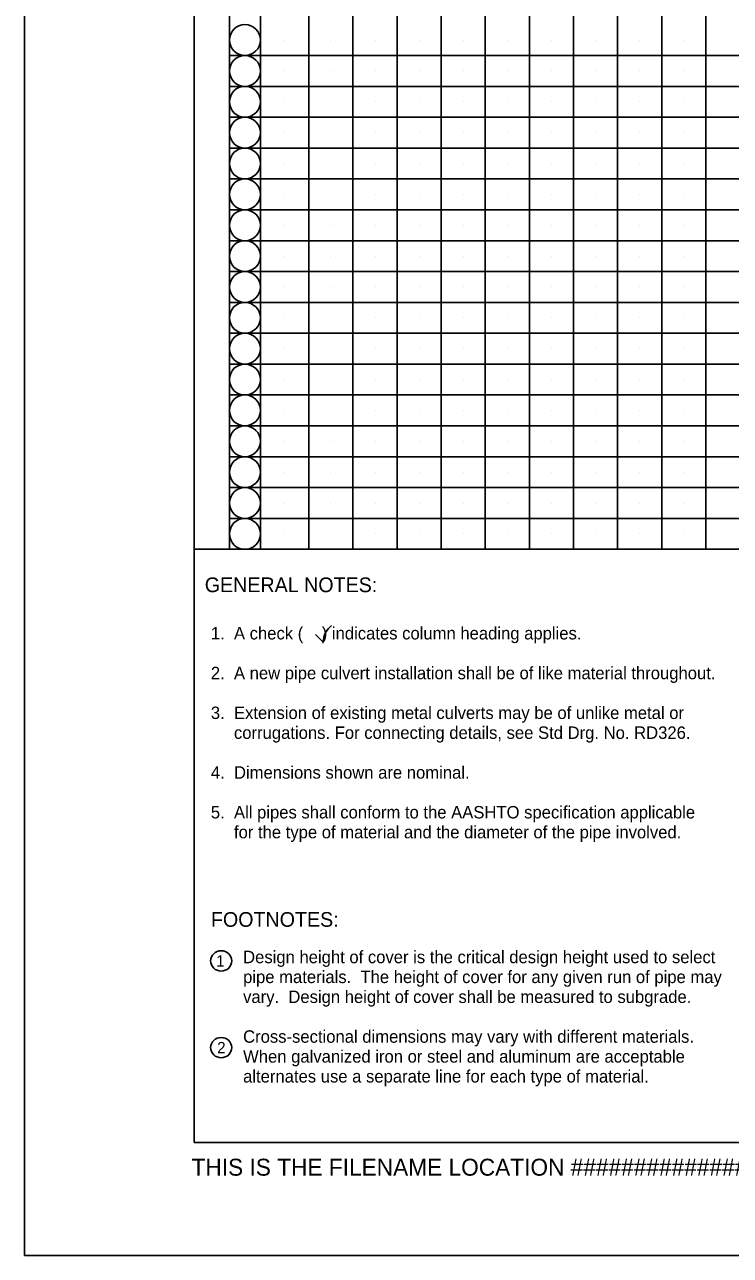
# Model space of a CAD drawing. Extents: x -1700 to 0, y 0 to 1100.
# Drawn here: x -1700 to -1388, y 0 to 545 of the extents above; entities that cross this region are included whole.
import ezdxf

# ---------------------------------------------------------------- set-up
doc = ezdxf.new("R2010")
doc.units = 0
for name, color, linetype in [('#plot_border', 7, 'Continuous'), ('#plot_shape', 7, 'Continuous'), ('P_ODOT_PLAN_Border', 7, 'Continuous'), ('P_ODOT_PLAN_General', 7, 'Continuous'), ('P_RDWY_PLAN_NotesTx', 7, 'Continuous')]:
    doc.layers.add(name, color=color, linetype=linetype)

msp = doc.modelspace()

# ---------------------------------------------------------------- linework, layer by layer
at = {"layer": '#plot_shape'}
msp.add_lwpolyline([(-1700, 0), (0, 0), (0, 1100), (-1700, 1100)], close=True, dxfattribs=at)
at = {"layer": 'P_ODOT_PLAN_Border'}
msp.add_lwpolyline([(-1625, 50), (-25, 50), (-25, 1050), (-1625, 1050)], close=True, dxfattribs=at)
at = {"layer": 'P_ODOT_PLAN_General'}
for p, q in [((-1609.39, 312.45), (-1609.39, 1050)), ((-1595.73, 312.45), (-1595.73, 1050)), ((-1574.27, 312.45), (-1574.27, 1050)), ((-1398.66, 312.45), (-1398.66, 1034.39)), ((-1554.76, 312.45), (-1554.76, 913.42)), ((-1535.24, 312.45), (-1535.24, 913.42)), ((-1515.73, 312.45), (-1515.73, 913.42)), ((-1496.22, 312.45), (-1496.22, 913.42)), ((-1476.71, 312.45), (-1476.71, 913.42)), ((-1457.2, 312.45), (-1457.2, 913.42)), ((-1437.68, 312.45), (-1437.68, 913.42)), ((-1418.17, 312.45), (-1418.17, 913.42)), ((-1585, 537.81), (-1585, 537.81)), ((-1564.51, 537.81), (-1564.51, 537.81)), ((-1545, 537.81), (-1545, 537.81)), ((-1525.49, 537.81), (-1525.49, 537.81)), ((-1505.98, 537.81), (-1505.98, 537.81)), ((-1486.46, 537.81), (-1486.46, 537.81)), ((-1466.95, 537.81), (-1466.95, 537.81)), ((-1447.44, 537.81), (-1447.44, 537.81)), ((-1427.93, 537.81), (-1427.93, 537.81)), ((-1408.42, 537.81), (-1408.42, 537.81)), ((-1398.66, 530.98), (-1609.39, 530.98)), ((-1088.42, 530.98), (-1398.66, 530.98)), ((-1585, 524.15), (-1585, 524.15)), ((-1564.51, 524.15), (-1564.51, 524.15)), ((-1545, 524.15), (-1545, 524.15)), ((-1525.49, 524.15), (-1525.49, 524.15)), ((-1505.98, 524.15), (-1505.98, 524.15)), ((-1486.46, 524.15), (-1486.46, 524.15)), ((-1466.95, 524.15), (-1466.95, 524.15)), ((-1447.44, 524.15), (-1447.44, 524.15)), ((-1427.93, 524.15), (-1427.93, 524.15)), ((-1408.42, 524.15), (-1408.42, 524.15)), ((-1398.66, 517.32), (-1609.39, 517.32)), ((-1088.42, 517.32), (-1398.66, 517.32)), ((-1585, 510.49), (-1585, 510.49)), ((-1564.51, 510.49), (-1564.51, 510.49)), ((-1545, 510.49), (-1545, 510.49)), ((-1525.49, 510.49), (-1525.49, 510.49)), ((-1505.98, 510.49), (-1505.98, 510.49)), ((-1486.46, 510.49), (-1486.46, 510.49)), ((-1466.95, 510.49), (-1466.95, 510.49)), ((-1447.44, 510.49), (-1447.44, 510.49)), ((-1427.93, 510.49), (-1427.93, 510.49)), ((-1408.42, 510.49), (-1408.42, 510.49)), ((-1398.66, 503.66), (-1609.39, 503.66)), ((-1088.42, 503.66), (-1398.66, 503.66)), ((-1585, 496.83), (-1585, 496.83)), ((-1564.51, 496.83), (-1564.51, 496.83)), ((-1545, 496.83), (-1545, 496.83)), ((-1525.49, 496.83), (-1525.49, 496.83)), ((-1505.98, 496.83), (-1505.98, 496.83)), ((-1486.46, 496.83), (-1486.46, 496.83)), ((-1466.95, 496.83), (-1466.95, 496.83)), ((-1447.44, 496.83), (-1447.44, 496.83)), ((-1427.93, 496.83), (-1427.93, 496.83)), ((-1408.42, 496.83), (-1408.42, 496.83)), ((-1398.66, 490.01), (-1609.39, 490.01)), ((-1088.42, 490.01), (-1398.66, 490.01)), ((-1585, 483.18), (-1585, 483.18)), ((-1564.51, 483.18), (-1564.51, 483.18)), ((-1545, 483.18), (-1545, 483.18)), ((-1525.49, 483.18), (-1525.49, 483.18)), ((-1505.98, 483.18), (-1505.98, 483.18)), ((-1486.46, 483.18), (-1486.46, 483.18)), ((-1466.95, 483.18), (-1466.95, 483.18)), ((-1447.44, 483.18), (-1447.44, 483.18)), ((-1427.93, 483.18), (-1427.93, 483.18)), ((-1408.42, 483.18), (-1408.42, 483.18)), ((-1398.66, 476.35), (-1609.39, 476.35)), ((-1088.42, 476.35), (-1398.66, 476.35)), ((-1585, 469.52), (-1585, 469.52)), ((-1564.51, 469.52), (-1564.51, 469.52)), ((-1545, 469.52), (-1545, 469.52)), ((-1525.49, 469.52), (-1525.49, 469.52)), ((-1505.98, 469.52), (-1505.98, 469.52)), ((-1486.46, 469.52), (-1486.46, 469.52)), ((-1466.95, 469.52), (-1466.95, 469.52)), ((-1447.44, 469.52), (-1447.44, 469.52)), ((-1427.93, 469.52), (-1427.93, 469.52)), ((-1408.42, 469.52), (-1408.42, 469.52)), ((-1398.66, 462.69), (-1609.39, 462.69)), ((-1088.42, 462.69), (-1398.66, 462.69)), ((-1585, 455.86), (-1585, 455.86)), ((-1564.51, 455.86), (-1564.51, 455.86)), ((-1545, 455.86), (-1545, 455.86)), ((-1525.49, 455.86), (-1525.49, 455.86)), ((-1505.98, 455.86), (-1505.98, 455.86)), ((-1486.46, 455.86), (-1486.46, 455.86)), ((-1466.95, 455.86), (-1466.95, 455.86)), ((-1447.44, 455.86), (-1447.44, 455.86)), ((-1427.93, 455.86), (-1427.93, 455.86)), ((-1408.42, 455.86), (-1408.42, 455.86)), ((-1398.66, 449.03), (-1609.39, 449.03)), ((-1088.42, 449.03), (-1398.66, 449.03)), ((-1585, 442.2), (-1585, 442.2)), ((-1564.51, 442.2), (-1564.51, 442.2)), ((-1545, 442.2), (-1545, 442.2)), ((-1525.49, 442.2), (-1525.49, 442.2)), ((-1505.98, 442.2), (-1505.98, 442.2)), ((-1486.46, 442.2), (-1486.46, 442.2)), ((-1466.95, 442.2), (-1466.95, 442.2)), ((-1447.44, 442.2), (-1447.44, 442.2)), ((-1427.93, 442.2), (-1427.93, 442.2)), ((-1408.42, 442.2), (-1408.42, 442.2)), ((-1398.66, 435.37), (-1609.39, 435.37)), ((-1088.42, 435.37), (-1398.66, 435.37)), ((-1585, 428.54), (-1585, 428.54)), ((-1564.51, 428.54), (-1564.51, 428.54)), ((-1545, 428.54), (-1545, 428.54)), ((-1525.49, 428.54), (-1525.49, 428.54)), ((-1505.98, 428.54), (-1505.98, 428.54)), ((-1486.46, 428.54), (-1486.46, 428.54)), ((-1466.95, 428.54), (-1466.95, 428.54)), ((-1447.44, 428.54), (-1447.44, 428.54)), ((-1427.93, 428.54), (-1427.93, 428.54)), ((-1408.42, 428.54), (-1408.42, 428.54)), ((-1398.66, 421.71), (-1609.39, 421.71)), ((-1088.42, 421.71), (-1398.66, 421.71)), ((-1585, 414.88), (-1585, 414.88)), ((-1564.51, 414.88), (-1564.51, 414.88)), ((-1545, 414.88), (-1545, 414.88)), ((-1525.49, 414.88), (-1525.49, 414.88)), ((-1505.98, 414.88), (-1505.98, 414.88)), ((-1486.46, 414.88), (-1486.46, 414.88)), ((-1466.95, 414.88), (-1466.95, 414.88)), ((-1447.44, 414.88), (-1447.44, 414.88)), ((-1427.93, 414.88), (-1427.93, 414.88)), ((-1408.42, 414.88), (-1408.42, 414.88)), ((-1398.66, 408.06), (-1609.39, 408.06)), ((-1088.42, 408.06), (-1398.66, 408.06)), ((-1585, 401.23), (-1585, 401.23)), ((-1564.51, 401.23), (-1564.51, 401.23)), ((-1545, 401.23), (-1545, 401.23)), ((-1525.49, 401.23), (-1525.49, 401.23)), ((-1505.98, 401.23), (-1505.98, 401.23)), ((-1486.46, 401.23), (-1486.46, 401.23)), ((-1466.95, 401.23), (-1466.95, 401.23)), ((-1447.44, 401.23), (-1447.44, 401.23)), ((-1427.93, 401.23), (-1427.93, 401.23)), ((-1408.42, 401.23), (-1408.42, 401.23)), ((-1398.66, 394.4), (-1609.39, 394.4)), ((-1088.42, 394.4), (-1398.66, 394.4)), ((-1585, 387.57), (-1585, 387.57)), ((-1564.51, 387.57), (-1564.51, 387.57)), ((-1545, 387.57), (-1545, 387.57)), ((-1525.49, 387.57), (-1525.49, 387.57)), ((-1505.98, 387.57), (-1505.98, 387.57)), ((-1486.46, 387.57), (-1486.46, 387.57)), ((-1466.95, 387.57), (-1466.95, 387.57)), ((-1447.44, 387.57), (-1447.44, 387.57)), ((-1427.93, 387.57), (-1427.93, 387.57)), ((-1408.42, 387.57), (-1408.42, 387.57)), ((-1398.66, 380.74), (-1609.39, 380.74)), ((-1088.42, 380.74), (-1398.66, 380.74)), ((-1585, 373.91), (-1585, 373.91)), ((-1564.51, 373.91), (-1564.51, 373.91)), ((-1545, 373.91), (-1545, 373.91)), ((-1525.49, 373.91), (-1525.49, 373.91)), ((-1505.98, 373.91), (-1505.98, 373.91)), ((-1486.46, 373.91), (-1486.46, 373.91)), ((-1466.95, 373.91), (-1466.95, 373.91)), ((-1447.44, 373.91), (-1447.44, 373.91)), ((-1427.93, 373.91), (-1427.93, 373.91)), ((-1408.42, 373.91), (-1408.42, 373.91)), ((-1398.66, 367.08), (-1609.39, 367.08)), ((-1088.42, 367.08), (-1398.66, 367.08)), ((-1585, 360.25), (-1585, 360.25)), ((-1564.51, 360.25), (-1564.51, 360.25)), ((-1545, 360.25), (-1545, 360.25)), ((-1525.49, 360.25), (-1525.49, 360.25)), ((-1505.98, 360.25), (-1505.98, 360.25)), ((-1486.46, 360.25), (-1486.46, 360.25)), ((-1466.95, 360.25), (-1466.95, 360.25)), ((-1447.44, 360.25), (-1447.44, 360.25)), ((-1427.93, 360.25), (-1427.93, 360.25)), ((-1408.42, 360.25), (-1408.42, 360.25)), ((-1398.66, 353.42), (-1609.39, 353.42)), ((-1088.42, 353.42), (-1398.66, 353.42)), ((-1585, 346.59), (-1585, 346.59)), ((-1564.51, 346.59), (-1564.51, 346.59)), ((-1545, 346.59), (-1545, 346.59)), ((-1525.49, 346.59), (-1525.49, 346.59)), ((-1505.98, 346.59), (-1505.98, 346.59)), ((-1486.46, 346.59), (-1486.46, 346.59)), ((-1466.95, 346.59), (-1466.95, 346.59)), ((-1447.44, 346.59), (-1447.44, 346.59)), ((-1427.93, 346.59), (-1427.93, 346.59)), ((-1408.42, 346.59), (-1408.42, 346.59)), ((-1398.66, 339.76), (-1609.39, 339.76)), ((-1088.42, 339.76), (-1398.66, 339.76)), ((-1585, 332.93), (-1585, 332.93)), ((-1564.51, 332.93), (-1564.51, 332.93)), ((-1545, 332.93), (-1545, 332.93)), ((-1525.49, 332.93), (-1525.49, 332.93)), ((-1505.98, 332.93), (-1505.98, 332.93)), ((-1486.46, 332.93), (-1486.46, 332.93)), ((-1466.95, 332.93), (-1466.95, 332.93)), ((-1447.44, 332.93), (-1447.44, 332.93)), ((-1427.93, 332.93), (-1427.93, 332.93)), ((-1408.42, 332.93), (-1408.42, 332.93)), ((-1398.66, 326.1), (-1609.39, 326.1)), ((-1088.42, 326.1), (-1398.66, 326.1)), ((-1585, 319.28), (-1585, 319.28)), ((-1564.51, 319.28), (-1564.51, 319.28)), ((-1545, 319.28), (-1545, 319.28)), ((-1525.49, 319.28), (-1525.49, 319.28)), ((-1505.98, 319.28), (-1505.98, 319.28)), ((-1486.46, 319.28), (-1486.46, 319.28)), ((-1466.95, 319.28), (-1466.95, 319.28)), ((-1447.44, 319.28), (-1447.44, 319.28)), ((-1427.93, 319.28), (-1427.93, 319.28)), ((-1408.42, 319.28), (-1408.42, 319.28)), ((-25.02, 312.45), (-1625, 312.45))]:
    msp.add_line(p, q, dxfattribs=at)
for centre in [(-1602.56, 537.81), (-1602.56, 524.15), (-1602.56, 510.49), (-1602.56, 496.83), (-1602.56, 483.18), (-1602.56, 469.52), (-1602.56, 455.86), (-1602.56, 442.2), (-1602.56, 428.54), (-1602.56, 414.88), (-1602.56, 401.23), (-1602.56, 387.57), (-1602.56, 373.91), (-1602.56, 360.25), (-1602.56, 346.59), (-1602.56, 332.93), (-1602.56, 319.28)]:
    msp.add_circle(centre, 6.83, dxfattribs=at)
at = {"layer": 'P_RDWY_PLAN_NotesTx'}
msp.add_lwpolyline([(-1571.34, 274.8), (-1568.23, 271.66), (-1568.01, 271.87), (-1567.56, 274.22), (-1566.86, 275.69), (-1565.72, 277.25), (-1564.23, 278.73)], dxfattribs=at)
for centre in [(-1613.05, 130.3), (-1613.05, 91.94)]:
    msp.add_ellipse(centre, major_axis=(4.68, 0), ratio=0.960077, dxfattribs=at)

# ---------------------------------------------------------------- texts
at = {"layer": '#plot_border'}
msp.add_text('THIS IS THE FILENAME LOCATION ##############################     DD-MMM-YYYY  HH:MM     USERNAME', height=7.5, dxfattribs=at).set_placement((-1626.17, 35.27))
at = {"layer": 'P_RDWY_PLAN_NotesTx'}
for s, height, p in [('GENERAL NOTES:', 6.5, (-1620.32, 293.49)), ('1.  A check (    ) indicates column heading applies.', 5.5, (-1617.62, 272.56)), ('2.  A new pipe culvert installation shall be of like material throughout.', 5.5, (-1617.62, 254.96)), ('3.  Extension of existing metal culverts may be of unlike metal or', 5.5, (-1617.62, 237.36)), ('     corrugations. For connecting details, see Std Drg. No. RD326.', 5.5, (-1617.62, 228.56)), ('4.  Dimensions shown are nominal.', 5.5, (-1617.62, 210.96)), ('5.  All pipes shall conform to the AASHTO specification applicable', 5.5, (-1617.62, 193.36)), ('     for the type of material and the diameter of the pipe involved.', 5.5, (-1617.62, 184.56)), ('FOOTNOTES:', 6.5, (-1617.59, 145.41)), ('1', 5, (-1615.29, 127.79)), ('Design height of cover is the critical design height used to select', 5.5, (-1603.36, 129.3)), ('pipe materials.  The height of cover for any given run of pipe may', 5.5, (-1603.36, 120.5)), ('vary.  Design height of cover shall be measured to subgrade.', 5.5, (-1603.36, 111.7)), ('Cross-sectional dimensions may vary with different materials.', 5.5, (-1603.36, 94.1)), ('2', 5, (-1614.83, 89.44)), ('When galvanized iron or steel and aluminum are acceptable', 5.5, (-1603.36, 85.3)), ('alternates use a separate line for each type of material.', 5.5, (-1603.36, 76.5))]:
    msp.add_text(s, height=height, dxfattribs=at).set_placement(p)

doc.saveas('drawing.dxf')
